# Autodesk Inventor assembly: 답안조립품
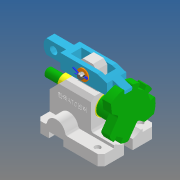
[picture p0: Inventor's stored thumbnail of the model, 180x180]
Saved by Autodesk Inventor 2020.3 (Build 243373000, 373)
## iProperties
Created: 2022-08
Part Number: 답안조립품
Document SubType Name: Assembly
Designer: EZDESIGN
Author: EZDESIGN
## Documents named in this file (8)
- Y:\720806V1001\답안조립품.iam
- Y:\720806V1001\본체.ipt
- Y:\720806V1001\부시.ipt
- Y:\720806V1001\분할대.ipt
- Y:\720806V1001\분할축.ipt
- Y:\720806V1001\분할핀.ipt
- Y:\720806V1001\와셔.ipt
- Y:\720806V1001\클레비스핀.ipt
